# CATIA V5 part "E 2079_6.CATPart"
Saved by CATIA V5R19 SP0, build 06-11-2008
Nomenclature: E 2079_6
Description: PART-E 2079_6-DESC
Property "Hersteller": "Meusburger"
Property "Material": "2.0401 / FPM (Viton)"
Property "Bestellnummer": "E2079/6"
Property "Teilenummer": "E2079/6"
Property "Beschreibung": "Verschlussstopfen mit O-Ring _ Plug with O-ring seal"
Material "Brass": density 8216 kg/m3, Young's modulus 1.31e+11 Pa, Poisson ratio 0.35, thermal expansion 1.67e-05 1/K
Bounding box of the stored display mesh (mm): x -3 to 3, y -3 to 3, z -10 to 0
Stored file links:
  G:\UTB\Kombinované\Bakalářská práce\Catia\FORMA\E 2079_6.CATPart
  D:\Aplikace\CATIA\Nová složka\win_b64\startup\materials\Catalog.CATMaterial
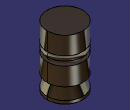
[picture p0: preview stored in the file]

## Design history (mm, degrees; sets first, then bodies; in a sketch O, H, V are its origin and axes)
Body1 "E 2079_6" (main body)
  Solid1: solid without history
